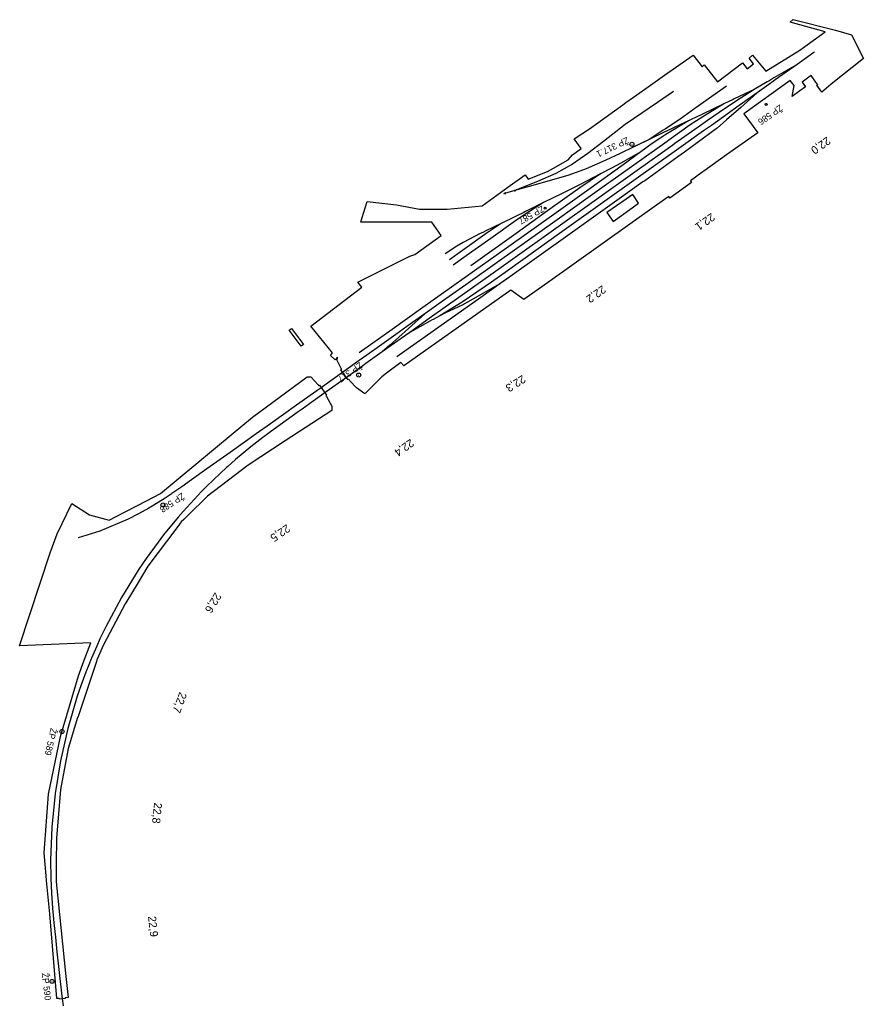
# Model space of a CAD drawing. Extents: x -792643 to -787072, y -1118436 to -1109677.
# Drawn here: x -792643 to -792010, y -1110414 to -1109677 of the extents above; entities that cross this region are included whole.
import ezdxf

# ---------------------------------------------------------------- set-up
doc = ezdxf.new("R2010")
doc.units = 0
for name, color, linetype in [('Vrstva 1', 7, 'Continuous'), ('Vrstva 2', 7, 'Continuous'), ('Vrstva 53', 7, 'Continuous'), ('Vrstva 63', 7, 'Continuous'), ('Vrstva 7', 7, 'Continuous')]:
    doc.layers.add(name, color=color, linetype=linetype)

msp = doc.modelspace()

# ---------------------------------------------------------------- linework, layer by layer
at = {"layer": 'Vrstva 1'}
for p, q in [((-792076.7, -1109721.08), (-792080.61, -1109723.39)), ((-792152.17, -1109731.19), (-792164.14, -1109739.57)), ((-792102.92, -1109735.09), (-792106.47, -1109736.78)), ((-792130.4, -1109748.19), (-792132.92, -1109749.41)), ((-792157.36, -1109761.01), (-792159.06, -1109761.82)), ((-792189.97, -1109786.25), (-792215.69, -1109804.67)), ((-792191.67, -1109785.07), (-792198.68, -1109788.87)), ((-792222.68, -1109801.33), (-792234.62, -1109807.29)), ((-792264.44, -1109821.87), (-792270.15, -1109824.64)), ((-792233.24, -1109840.5), (-792274.84, -1109870.12)), ((-792296.79, -1109885.76), (-792332.44, -1109911.06)), ((-792298.56, -1109884.62), (-792310.78, -1109891.36)), ((-792333.18, -1109902.52), (-792334.93, -1109903.38)), ((-792351.01, -1109908.99), (-792358.28, -1109915.51))]:
    msp.add_line(p, q, dxfattribs=at)
for points in [[(-792048.3, -1109703.11), (-792049.6, -1109704.04), (-792059.39, -1109711), (-792076.7, -1109721.08)], [(-792048.3, -1109703.11), (-792049.6, -1109704.04), (-792059.39, -1109711), (-792075.7, -1109722.58)], [(-792046.4, -1109701.77), (-792048.3, -1109703.11)], [(-792112.37, -1109727.15), (-792136.09, -1109744.11), (-792147.01, -1109751.93), (-792158.09, -1109759.21), (-792159.86, -1109760.34)], [(-792080.61, -1109723.39), (-792081.69, -1109724.02), (-792091.47, -1109729.8), (-792102.92, -1109735.09), (-792106.47, -1109736.78), (-792107.22, -1109737.14), (-792114.34, -1109740.53), (-792130.4, -1109748.19)], [(-792075.7, -1109722.58), (-792077.01, -1109723.52), (-792089.24, -1109732.21), (-792102.81, -1109741.85)], [(-792081.69, -1109724.02), (-792091.47, -1109729.8), (-792102.08, -1109736.54)], [(-792075.7, -1109722.58), (-792077.01, -1109723.52), (-792089.24, -1109732.21), (-792101.66, -1109743.28)], [(-792164.14, -1109739.57), (-792188.38, -1109755.97), (-792204.67, -1109768.8), (-792216.3, -1109777.78), (-792228.01, -1109785.68), (-792240.5, -1109792.68), (-792254.12, -1109798.75)], [(-792102.81, -1109741.85), (-792123.67, -1109756.66), (-792129.57, -1109760.85), (-792148.09, -1109774.02), (-792149.77, -1109775.22), (-792176.62, -1109794.3), (-792178.28, -1109795.48), (-792235.96, -1109836.57)], [(-792102.08, -1109736.54), (-792113.19, -1109743.78), (-792126.57, -1109752.93), (-792133.59, -1109757.92), (-792151.01, -1109770.32), (-792152.7, -1109771.52), (-792179.34, -1109790.45), (-792181.06, -1109791.69), (-792209.96, -1109812.25)], [(-792106.47, -1109736.78), (-792107.22, -1109737.14), (-792114.34, -1109740.53), (-792130.17, -1109750.23)], [(-792101.66, -1109743.28), (-792112.23, -1109752.61), (-792119.36, -1109758.66), (-792120.02, -1109759.19), (-792143.83, -1109776.79), (-792148.79, -1109780.33), (-792173.73, -1109798.13), (-792174.99, -1109799.02), (-792192.82, -1109811.74), (-792233.24, -1109840.5)], [(-792132.92, -1109749.41), (-792133.69, -1109749.79), (-792140.79, -1109753.15), (-792146.78, -1109755.98), (-792157.36, -1109761.01)], [(-792132.92, -1109749.41), (-792133.69, -1109749.79), (-792140.79, -1109753.15), (-792156.69, -1109762.85)], [(-792130.17, -1109750.23), (-792139.5, -1109756.34), (-792153.9, -1109766.48), (-792155.55, -1109767.65), (-792156.93, -1109768.63), (-792199.1, -1109798.65), (-792200.73, -1109799.82), (-792212.82, -1109808.4)], [(-792159.86, -1109760.34), (-792170.45, -1109767.27), (-792181.83, -1109772.71)], [(-792159.06, -1109761.82), (-792170.45, -1109767.27), (-792180.68, -1109772.16), (-792181.83, -1109772.71)], [(-792156.69, -1109762.85), (-792157.86, -1109763.59), (-792160.22, -1109765.12), (-792168.01, -1109770.37)], [(-792168.01, -1109770.37), (-792176.54, -1109776.54), (-792191.67, -1109785.07)], [(-792168.01, -1109770.37), (-792176.54, -1109776.54), (-792189.97, -1109786.25)], [(-792181.83, -1109772.71), (-792192.24, -1109777.76), (-792202.93, -1109782.85), (-792217.54, -1109789.29), (-792230.61, -1109793.94), (-792254.25, -1109800.79)], [(-792198.68, -1109788.87), (-792206.85, -1109793.11), (-792222.68, -1109801.33)], [(-792198.68, -1109788.87), (-792206.85, -1109793.11), (-792222.38, -1109803.38)], [(-792254.12, -1109798.75), (-792271.17, -1109805.6), (-792279.01, -1109807.83), (-792279.55, -1109807.98)], [(-792254.25, -1109800.79), (-792271.17, -1109805.6), (-792279.01, -1109807.83), (-792279.55, -1109807.98)], [(-792215.69, -1109804.67), (-792243.72, -1109824.64), (-792285.26, -1109854.19), (-792301.39, -1109865.67), (-792340.23, -1109893.3)], [(-792212.82, -1109808.4), (-792241.25, -1109828.65), (-792282.66, -1109858.15), (-792308.02, -1109876.22), (-792322.95, -1109886.79), (-792325.41, -1109888.54)], [(-792222.38, -1109803.38), (-792246.6, -1109820.68), (-792270.21, -1109837.67), (-792304.07, -1109862.01)], [(-792234.62, -1109807.29), (-792236.05, -1109808), (-792249.55, -1109814.59), (-792263.14, -1109821.23), (-792264.44, -1109821.87)], [(-792234.62, -1109807.29), (-792236.05, -1109808), (-792249.55, -1109814.59), (-792263.55, -1109823.47)], [(-792209.96, -1109812.25), (-792238.66, -1109832.67), (-792279.73, -1109861.91), (-792304.68, -1109879.64), (-792335.48, -1109901.57)], [(-792263.55, -1109823.47), (-792270.58, -1109828.18), (-792289.27, -1109841.39), (-792307.71, -1109854.48), (-792317.52, -1109861.43)], [(-792270.15, -1109824.64), (-792271.29, -1109825.21), (-792281.48, -1109830.18), (-792292.85, -1109835.73)], [(-792270.15, -1109824.64), (-792271.29, -1109825.21), (-792281.48, -1109830.18), (-792292.02, -1109837.14)], [(-792292.85, -1109835.73), (-792295.26, -1109836.91), (-792297.09, -1109837.81), (-792310.01, -1109844.39), (-792314.68, -1109847.14), (-792323.5, -1109853.02)], [(-792292.02, -1109837.14), (-792310.51, -1109850.59), (-792320.24, -1109857.61)], [(-792235.96, -1109836.57), (-792276.65, -1109865.62), (-792288.67, -1109874.2), (-792310.79, -1109889.22)], [(-792274.84, -1109870.12), (-792276, -1109870.95), (-792282.35, -1109875.47), (-792298.56, -1109884.62)], [(-792274.84, -1109870.12), (-792276, -1109870.95), (-792282.35, -1109875.47), (-792296.79, -1109885.76)], [(-792325.41, -1109888.54), (-792326.36, -1109889.22), (-792338.62, -1109897.93), (-792352.16, -1109907.56)], [(-792325.41, -1109888.54), (-792326.36, -1109889.22), (-792338.62, -1109897.93), (-792351.01, -1109908.99)], [(-792310.79, -1109889.22), (-792327.49, -1109899.53), (-792332.48, -1109902.16), (-792333.18, -1109902.52)], [(-792340.23, -1109893.3), (-792363.31, -1109909.67), (-792387.97, -1109927.16)], [(-792310.78, -1109891.36), (-792323.19, -1109897.28), (-792327.49, -1109899.53), (-792332.48, -1109902.16), (-792333.18, -1109902.52)], [(-792335.48, -1109901.57), (-792350.03, -1109911.91), (-792356.41, -1109916.47), (-792357.13, -1109916.96), (-792370.68, -1109926.59), (-792382.92, -1109935.31), (-792384.22, -1109936.22)], [(-792334.93, -1109903.38), (-792350.03, -1109911.91), (-792356.41, -1109916.47), (-792357.13, -1109916.96)], [(-792352.16, -1109907.56), (-792360.35, -1109913.37), (-792372.75, -1109922.21), (-792382.31, -1109929)], [(-792332.44, -1109911.06), (-792359.63, -1109930.24)], [(-792358.28, -1109915.51), (-792365.02, -1109921.36), (-792370.68, -1109926.59), (-792382.92, -1109935.31), (-792384.22, -1109936.22)], [(-792382.31, -1109929), (-792388.05, -1109933.09), (-792399.54, -1109941.27), (-792417.36, -1109953.93), (-792424.86, -1109959.25), (-792436.72, -1109967.69)], [(-792384.22, -1109936.22), (-792385.23, -1109936.93), (-792396.78, -1109945.13), (-792414.59, -1109957.76), (-792422.59, -1109963.47), (-792430.84, -1109969.36)], [(-792436.72, -1109967.69), (-792454.58, -1109980.37), (-792465.32, -1109988), (-792484.84, -1110001.87), (-792502.26, -1110014.28), (-792513.73, -1110022.43)], [(-792430.84, -1109969.36), (-792433.88, -1109971.53), (-792451.75, -1109984.4), (-792460.28, -1109990.73), (-792469.28, -1109997.71)], [(-792469.28, -1109997.71), (-792480.84, -1110007.28), (-792486.67, -1110012.4), (-792487.56, -1110013.21), (-792497.16, -1110022.12), (-792502.93, -1110027.77), (-792506.24, -1110031.12), (-792520.16, -1110046.13), (-792523.85, -1110050.38), (-792534.85, -1110063.82), (-792538.95, -1110069.16), (-792547.81, -1110081.35), (-792553.26, -1110089.41), (-792566.31, -1110110.64), (-792578.12, -1110132.74), (-792582.48, -1110141.81), (-792584.96, -1110147.24), (-792588.85, -1110156.21), (-792589.02, -1110156.6), (-792590.9, -1110161.2), (-792593.03, -1110166.65), (-792596.56, -1110176.18), (-792599.51, -1110184.76), (-792606.63, -1110208.86), (-792612.18, -1110233.19), (-792616.22, -1110257.78), (-792618.75, -1110282.9), (-792619.62, -1110307.66), (-792619.45, -1110321.14), (-792618.95, -1110332.54)], [(-792513.73, -1110022.43), (-792521.17, -1110027.68), (-792528.46, -1110032.7), (-792529.08, -1110033.13), (-792533.56, -1110036.11), (-792538.72, -1110039.42), (-792543.37, -1110042.26), (-792545.73, -1110043.66), (-792553.52, -1110048.01), (-792561.34, -1110051.97)], [(-792561.34, -1110051.97), (-792582.59, -1110060.89), (-792598.87, -1110066.01)], [(-792618.95, -1110332.54), (-792618.13, -1110343.64), (-792617.13, -1110354.57), (-792615.98, -1110365.5), (-792614.76, -1110376.51)], [(-792614.76, -1110376.51), (-792611.02, -1110409.57), (-792610.2, -1110416.89)]]:
    msp.add_lwpolyline(points, dxfattribs=at)
at = {"layer": 'Vrstva 2'}
for p, q in [((-792059.39, -1109711), (-792075.7, -1109722.58)), ((-792091.47, -1109729.8), (-792102.08, -1109736.54)), ((-792089.24, -1109732.21), (-792101.66, -1109743.28)), ((-792114.34, -1109740.53), (-792130.17, -1109750.23)), ((-792140.79, -1109753.15), (-792156.69, -1109762.85)), ((-792159.86, -1109760.34), (-792170.45, -1109767.27)), ((-792176.54, -1109776.54), (-792191.67, -1109785.07)), ((-792206.85, -1109793.11), (-792222.38, -1109803.38)), ((-792254.12, -1109798.75), (-792271.17, -1109805.6)), ((-792249.55, -1109814.59), (-792263.55, -1109823.47)), ((-792281.48, -1109830.18), (-792292.02, -1109837.14)), ((-792282.35, -1109875.47), (-792298.56, -1109884.62)), ((-792338.62, -1109897.93), (-792351.01, -1109908.99)), ((-792334.93, -1109903.38), (-792350.03, -1109911.91))]:
    msp.add_line(p, q, dxfattribs=at)
for points in [[(-792048.3, -1109703.11), (-792049.6, -1109704.04), (-792059.39, -1109711), (-792076.7, -1109721.08)], [(-792080.61, -1109723.39), (-792081.69, -1109724.02), (-792091.47, -1109729.8), (-792102.92, -1109735.09)], [(-792075.7, -1109722.58), (-792077.01, -1109723.52), (-792089.24, -1109732.21), (-792102.81, -1109741.85)], [(-792106.47, -1109736.78), (-792107.22, -1109737.14), (-792114.34, -1109740.53), (-792130.4, -1109748.19)], [(-792132.92, -1109749.41), (-792133.69, -1109749.79), (-792140.79, -1109753.15), (-792146.78, -1109755.98), (-792157.36, -1109761.01)], [(-792159.06, -1109761.82), (-792170.45, -1109767.27), (-792180.68, -1109772.16), (-792181.83, -1109772.71)], [(-792168.01, -1109770.37), (-792176.54, -1109776.54), (-792189.97, -1109786.25)], [(-792198.68, -1109788.87), (-792206.85, -1109793.11), (-792222.68, -1109801.33)], [(-792254.25, -1109800.79), (-792271.17, -1109805.6), (-792279.01, -1109807.83), (-792279.55, -1109807.98)], [(-792278.15, -1109807.32), (-792279.01, -1109807.83), (-792278.01, -1109807.82)], [(-792234.62, -1109807.29), (-792236.05, -1109808), (-792249.55, -1109814.59), (-792263.14, -1109821.23), (-792264.44, -1109821.87)], [(-792270.15, -1109824.64), (-792271.29, -1109825.21), (-792281.48, -1109830.18), (-792292.85, -1109835.73)], [(-792274.84, -1109870.12), (-792282.35, -1109875.47), (-792296.79, -1109885.76)], [(-792325.41, -1109888.54), (-792326.36, -1109889.22), (-792338.62, -1109897.93), (-792352.16, -1109907.56)], [(-792310.79, -1109889.22), (-792326.11, -1109898.68), (-792327.49, -1109899.53), (-792332.48, -1109902.16), (-792333.18, -1109902.52)], [(-792310.78, -1109891.36), (-792323.19, -1109897.28), (-792327.49, -1109899.53)], [(-792335.48, -1109901.57), (-792350.03, -1109911.91), (-792356.41, -1109916.47), (-792357.13, -1109916.96)], [(-792357.13, -1109916.96), (-792370.68, -1109926.59), (-792382.92, -1109935.31), (-792384.22, -1109936.22)], [(-792358.28, -1109915.51), (-792365.02, -1109921.36), (-792370.68, -1109926.59)]]:
    msp.add_lwpolyline(points, dxfattribs=at)
msp.add_circle((-792271.17, -1109805.6), 0.4, dxfattribs=at)
at = {"layer": 'Vrstva 53'}
for points in [[(-792038.26, -1109686.52), (-792064.43, -1109679.2), (-792062.33, -1109677.36), (-792030.44, -1109685.15), (-792018.46, -1109688.78), (-792009.6, -1109706.46)], [(-792363.55, -1109861.57), (-792349.96, -1109854.83), (-792346.23, -1109853.43), (-792326.43, -1109839.17), (-792333.34, -1109829.35), (-792386.68, -1109829.15), (-792385.8, -1109825.7), (-792381.95, -1109813.67), (-792359.93, -1109816.17), (-792342.61, -1109819.6), (-792322.02, -1109819.61), (-792295.56, -1109816.94), (-792276.34, -1109803.1), (-792263.48, -1109793.72), (-792261.09, -1109796.98), (-792246.57, -1109791.13), (-792242.15, -1109788.7), (-792231.12, -1109782.39), (-792227.91, -1109778.64), (-792221.5, -1109774), (-792226.53, -1109766.83), (-792215.1, -1109759.26), (-792190.07, -1109741.13), (-792187.8, -1109739.49), (-792182.21, -1109735.57), (-792171.12, -1109727.8), (-792158.73, -1109719.12), (-792137.25, -1109704.07), (-792130.48, -1109712.65), (-792129.14, -1109711.27), (-792119.15, -1109724.06), (-792100.25, -1109709.81), (-792096.91, -1109714.15), (-792092.06, -1109710.49), (-792095.42, -1109706.17), (-792092.71, -1109704.13), (-792082.74, -1109715.97), (-792057.33, -1109700.37), (-792051.73, -1109696.36), (-792038.26, -1109686.52)], [(-792009.6, -1109706.46), (-792033.77, -1109725.73), (-792040.87, -1109731.66), (-792044.51, -1109726.58), (-792043.88, -1109726.16), (-792045.28, -1109724.14), (-792048.16, -1109719.98), (-792048.66, -1109719.25), (-792050.55, -1109720.58), (-792055.65, -1109724.16), (-792052.97, -1109727.83), (-792057.17, -1109730.8), (-792063.04, -1109734.91), (-792061.45, -1109726.78), (-792064.44, -1109722.94), (-792099.3, -1109747.92), (-792088.89, -1109762.3), (-792112.22, -1109778.74), (-792129.24, -1109790.96), (-792130.77, -1109792.06), (-792139.4, -1109798.31), (-792138.54, -1109799.49), (-792154.86, -1109811.14), (-792155.68, -1109810), (-792164.73, -1109816.44), (-792246.55, -1109874.61), (-792264.32, -1109887.25), (-792274.06, -1109880.18)], [(-792274.06, -1109880.18), (-792354.59, -1109937.05), (-792356.82, -1109934.38), (-792367.46, -1109942.54), (-792370.89, -1109945.17), (-792383.68, -1109958.07), (-792389.98, -1109953.44), (-792394.9, -1109948.21), (-792395.36, -1109947.72), (-792395.96, -1109947.08), (-792396.36, -1109947.46), (-792401.63, -1109940.01), (-792401.09, -1109939.74), (-792401.42, -1109939.07), (-792404.43, -1109932.95), (-792404.35, -1109930.54), (-792406.09, -1109932.53), (-792409.46, -1109929.26), (-792407.99, -1109927.32), (-792424.2, -1109907.16), (-792385.97, -1109878.06), (-792389.09, -1109874.23), (-792363.55, -1109861.57)], [(-792619.92, -1110077.28), (-792614.54, -1110062.94), (-792603.7, -1110040.3), (-792590.28, -1110048.67), (-792575.7, -1110052.69), (-792570.38, -1110049.94), (-792547.64, -1110038.22), (-792537.18, -1110032.76), (-792484.01, -1109988.67), (-792468.07, -1109975.45), (-792427.01, -1109945.27), (-792424.33, -1109945.11), (-792418.77, -1109951.27), (-792418.22, -1109951.87), (-792417.83, -1109951.51), (-792412.51, -1109959), (-792413, -1109959.27), (-792412.59, -1109960.02), (-792408.62, -1109967.32), (-792408.62, -1109969.07), (-792408.62, -1109970.51), (-792443.53, -1109993.3), (-792471.37, -1110011.46), (-792501.89, -1110034.83), (-792516.81, -1110049.41), (-792519.67, -1110052.2), (-792521.55, -1110054.04), (-792524.19, -1110057.53), (-792546.69, -1110087.26), (-792553.88, -1110099.37), (-792562.99, -1110114.71), (-792563.49, -1110115.56), (-792579.9, -1110146.2), (-792584.67, -1110156.97), (-792585.44, -1110159.39), (-792598.98, -1110199.86), (-792599.26, -1110200.78), (-792606.33, -1110223.88), (-792612.21, -1110254.77), (-792615.1, -1110291.3), (-792615.1, -1110292.2), (-792615.25, -1110309.12), (-792615.38, -1110323.92), (-792608.17, -1110395.02), (-792606.36, -1110410.71), (-792608.74, -1110410.94), (-792608.68, -1110411.53), (-792612.94, -1110412.04), (-792613.01, -1110411.35), (-792614.81, -1110411.53), (-792620.21, -1110347.82), (-792622.68, -1110323), (-792622.83, -1110319.49), (-792624.38, -1110302.15), (-792621.16, -1110258.14), (-792612.04, -1110215.02), (-792598.72, -1110169.4), (-792594.35, -1110157.78), (-792589.4, -1110144.63), (-792642.8, -1110147.06), (-792619.92, -1110077.28)]]:
    msp.add_lwpolyline(points, dxfattribs=at)
for points in [[(-792182.67, -1109808.46), (-792187.68, -1109812.04), (-792202.2, -1109822.1), (-792197.4, -1109828.81), (-792183.19, -1109818.5), (-792178.27, -1109814.93)], [(-792440.51, -1109910.24), (-792438.83, -1109908.9), (-792429.71, -1109920.9), (-792431.42, -1109922.33)]]:
    msp.add_lwpolyline(points, close=True, dxfattribs=at)
at = {"layer": 'Vrstva 63'}
for p, q in [((-792082.67, -1109740.89), (-792082.57, -1109740.89)), ((-792183.36, -1109770.88), (-792183.16, -1109770.88)), ((-792248.48, -1109818.75), (-792248.38, -1109818.75)), ((-792388.43, -1109943.91), (-792388.23, -1109943.91)), ((-792535.37, -1110041.31), (-792535.17, -1110041.31)), ((-792611.1, -1110211.18), (-792610.9, -1110211.18)), ((-792618.61, -1110398.65), (-792618.41, -1110398.65))]:
    msp.add_line(p, q, dxfattribs=at)
for centre, radius in [((-792082.62, -1109740.89), 0.756), ((-792183.26, -1109770.88), 1.51), ((-792248.43, -1109818.75), 0.756), ((-792388.33, -1109943.91), 1.51), ((-792535.27, -1110041.31), 1.51), ((-792611, -1110211.18), 1.51), ((-792618.51, -1110398.65), 1.51)]:
    msp.add_circle(centre, radius, dxfattribs=at)

# ---------------------------------------------------------------- texts
for s, rotation, p in [('ŽP 586', 215.36918, (-792072.35, -1109740.83)), ('ŽP 317.1', 205.85003, (-792187.13, -1109765.19)), ('ŽP 587', 209.87384, (-792250.88, -1109816.64)), ('ŽP 317', 215.45329, (-792387.76, -1109933.88)), ('ŽP 588', 213.72115, (-792521.01, -1110031.9)), ('ŽP 589', 257.15646, (-792619.47, -1110208.32)), ('ŽP 590', 276.44555, (-792626.17, -1110392.46))]:
    msp.add_text(s, height=4.8, rotation=rotation, dxfattribs=at).set_placement(p)
at = {"layer": 'Vrstva 7'}
for s, rotation, p in [('22,0', 215.40383, (-792036.89, -1109764.83)), ('22,1', 215.39793, (-792123.75, -1109822.08)), ('22,2', 215.46516, (-792205.52, -1109876.32)), ('22,3', 212.3274, (-792265.48, -1109943.61)), ('22,4', 215.36095, (-792349.52, -1109991.48)), ('22,5', 214.60279, (-792442.44, -1110055.56)), ('22,6', 238.99526, (-792496.05, -1110106.5)), ('22,7', 249.6626, (-792522.71, -1110181.2)), ('22,8', 264.25328, (-792541.84, -1110264.35)), ('22,9', 276.3659, (-792546.46, -1110349.98))]:
    msp.add_text(s, height=6, rotation=rotation, dxfattribs=at).set_placement(p)

doc.saveas('drawing.dxf')
